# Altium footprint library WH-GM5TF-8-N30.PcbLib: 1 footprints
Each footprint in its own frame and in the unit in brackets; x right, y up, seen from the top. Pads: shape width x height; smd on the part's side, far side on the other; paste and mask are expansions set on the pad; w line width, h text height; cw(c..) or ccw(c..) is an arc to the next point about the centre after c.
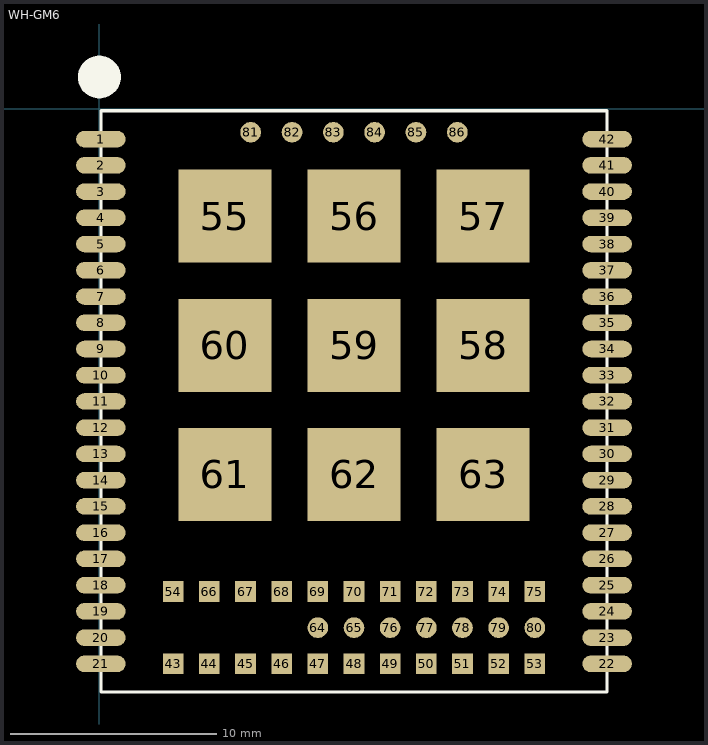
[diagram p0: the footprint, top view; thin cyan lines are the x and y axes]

## WH-GM6 [mm]
pads (86):
  oval 2.4x0.8 smd mask+0.025: 1(0.082,-1.467) 2(0.082,-2.737) 3(0.082,-4.007) 4(0.082,-5.277) 5(0.082,-6.547) 6(0.082,-7.817) 7(0.082,-9.087) 8(0.082,-10.357) 9(0.082,-11.627) 10(0.082,-12.897) 11(0.082,-14.167) 12(0.082,-15.437) 13(0.082,-16.707) 14(0.082,-17.977) 15(0.082,-19.247) 16(0.082,-20.517) 17(0.082,-21.787) 18(0.082,-23.057) 19(0.082,-24.327) 20(0.082,-25.597) 21(0.082,-26.867) 22(24.582,-26.867) 23(24.582,-25.597) 24(24.582,-24.327) 25(24.582,-23.057) 26(24.582,-21.787) 27(24.582,-20.517) 28(24.582,-19.247) 29(24.582,-17.977) 30(24.582,-16.707) 31(24.582,-15.437) 32(24.582,-14.167) 33(24.582,-12.897) 34(24.582,-11.627) 35(24.582,-10.357) 36(24.582,-9.087) 37(24.582,-7.817) 38(24.582,-6.547) 39(24.582,-5.277) 40(24.582,-4.007) 41(24.582,-2.737) 42(24.582,-1.467)
  rect 1x1 smd mask+0.025: 43(3.582,-26.867) 44(5.332,-26.867) 45(7.082,-26.867) 46(8.832,-26.867) 47(10.582,-26.867) 48(12.332,-26.867) 49(14.082,-26.867) 50(15.832,-26.867) 51(17.582,-26.867) 52(19.332,-26.867) 53(21.082,-26.867) 54(3.582,-23.367) 66(5.332,-23.367) 67(7.082,-23.367) 68(8.832,-23.367) 69(10.582,-23.367) 70(12.332,-23.367) 71(14.082,-23.367) 72(15.832,-23.367) 73(17.582,-23.367) 74(19.332,-23.367) 75(21.082,-23.367)
  rect 4.5x4.5 smd mask+0.025: 55(6.082,-5.197) 56(12.332,-5.197) 57(18.582,-5.197) 58(18.582,-11.447) 59(12.332,-11.447) 60(6.082,-11.447) 61(6.082,-17.697) 62(12.332,-17.697) 63(18.582,-17.697)
  round 1 smd mask+0.025: 64(10.582,-25.117) 65(12.332,-25.117) 76(14.082,-25.117) 77(15.832,-25.117) 78(17.582,-25.117) 79(19.332,-25.117) 80(21.082,-25.117) 81(7.332,-1.137) 82(9.332,-1.137) 83(11.332,-1.137) 84(13.332,-1.137) 85(15.332,-1.137) 86(17.332,-1.137)
Top Overlay:
  region: 1.033,1.537 1.033,1.638 0.994,1.836 0.917,2.023 0.804,2.191 0.661,2.334 0.493,2.446 0.307,2.524 0.109,2.563 0.008,2.563 -0.093,2.563 -0.291,2.524 -0.478,2.446 -0.646,2.334 -0.789,2.191 -0.901,2.023 -0.979,1.836 -1.018,1.638 -1.018,1.537 -1.018,1.436 -0.979,1.238 -0.901,1.052 -0.789,0.884 -0.646,0.741 -0.478,0.628 -0.291,0.551 -0.093,0.512 0.008,0.512 0.109,0.512 0.307,0.551 0.493,0.628 0.661,0.741 0.804,0.884 0.917,1.052 0.994,1.238 1.033,1.436
  lines w0.15: 0.082,-28.237 0.082,-0.097 24.582,-0.097 24.582,-28.237 0.082,-28.237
